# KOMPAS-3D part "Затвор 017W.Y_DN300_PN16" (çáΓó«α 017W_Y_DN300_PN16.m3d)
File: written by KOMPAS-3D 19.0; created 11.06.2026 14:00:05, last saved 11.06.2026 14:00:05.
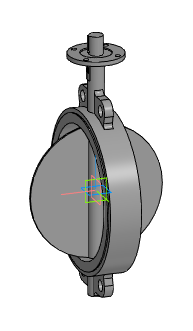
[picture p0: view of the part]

Document properties: Автор: Евгений; Полное имя файла: Z:\3.Личные\kachalov\001_3d для проектировщиков\x.x Тип 017W.Y(S) Затвор дисковый поворотный межфланцевый\_stp_Затвор 017W.Y_DN50-DN350\Затвор 017W_Y_DN300_PN16.m3d

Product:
- Part/product: Затвор 017W.Y_DN300_PN16

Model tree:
1. Операция без истории:1  (labels: Затвор 017W.Y_DN300_PN16)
